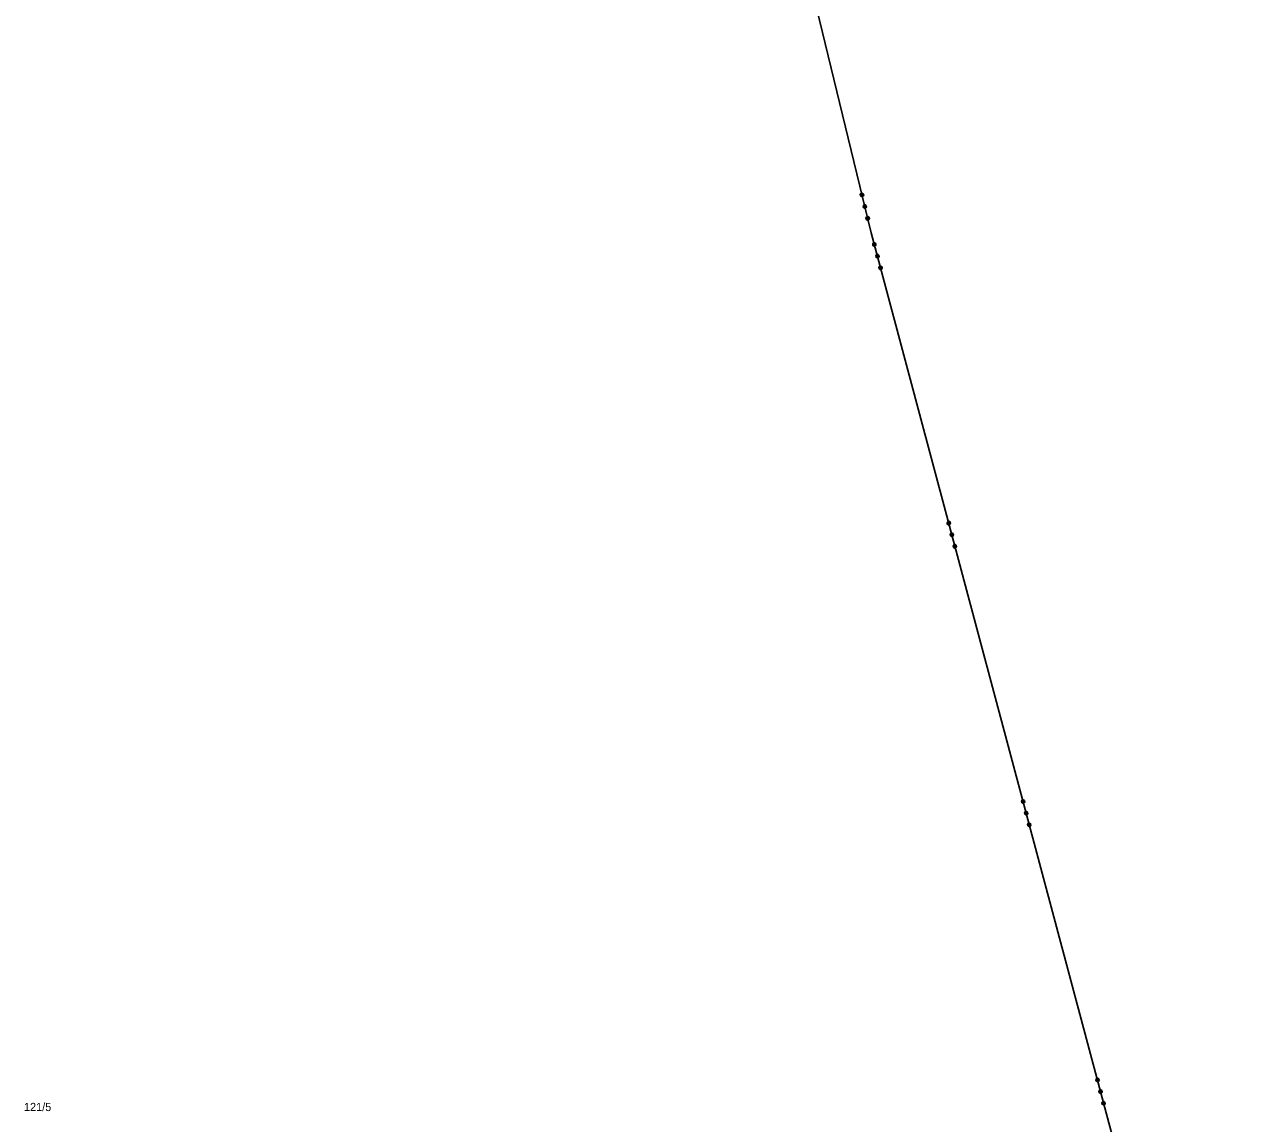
# Model space of a CAD drawing. Extents: x -757994 to -755874, y -1047691 to -1046119.
# Drawn here: x -756034.7 to -755905.7, y -1046848.6 to -1046734.2 of the extents above; entities that cross this region are included whole.
import ezdxf

# ---------------------------------------------------------------- set-up
doc = ezdxf.new("R2010")
doc.units = 0
doc.layers.add('katastrální mapa', color=7, linetype='Continuous')

msp = doc.modelspace()

# ---------------------------------------------------------------- linework, layer by layer
at = {"layer": 'katastrální mapa'}
for p, q in [((-755983.3, -1046604.98), (-755946.55, -1046755.9)), ((-755946.55, -1046755.9), (-755905.73, -1046908.68))]:
    msp.add_line(p, q, dxfattribs=at)
for points in [[(-755947.34, -1046751.96), (-755947.41, -1046752.08), (-755947.55, -1046752.11), (-755947.66, -1046752.04), (-755947.69, -1046751.91), (-755947.62, -1046751.79), (-755947.49, -1046751.76), (-755947.38, -1046751.83), (-755947.34, -1046751.96), (-755947.36, -1046751.97), (-755947.39, -1046751.85), (-755947.44, -1046751.82), (-755947.39, -1046752.02), (-755947.42, -1046752.06), (-755947.49, -1046751.8), (-755947.53, -1046751.8), (-755947.46, -1046752.06), (-755947.5, -1046752.08), (-755947.56, -1046751.82), (-755947.6, -1046751.83), (-755947.54, -1046752.09), (-755947.58, -1046752.07), (-755947.64, -1046751.86), (-755947.67, -1046751.91), (-755947.63, -1046752.04)], [(-755947.05, -1046753.18), (-755947.12, -1046753.3), (-755947.25, -1046753.33), (-755947.36, -1046753.26), (-755947.4, -1046753.13), (-755947.33, -1046753.01), (-755947.19, -1046752.98), (-755947.08, -1046753.05), (-755947.05, -1046753.18), (-755947.07, -1046753.18), (-755947.1, -1046753.06), (-755947.14, -1046753.03), (-755947.1, -1046753.23), (-755947.13, -1046753.28), (-755947.19, -1046753), (-755947.23, -1046753.01), (-755947.17, -1046753.29), (-755947.2, -1046753.3), (-755947.27, -1046753.02), (-755947.31, -1046753.03), (-755947.24, -1046753.31), (-755947.29, -1046753.28), (-755947.34, -1046753.08), (-755947.37, -1046753.13), (-755947.34, -1046753.25)], [(-755946.75, -1046754.4), (-755946.82, -1046754.51), (-755946.95, -1046754.55), (-755947.07, -1046754.48), (-755947.1, -1046754.35), (-755947.03, -1046754.23), (-755946.9, -1046754.2), (-755946.78, -1046754.27), (-755946.75, -1046754.4), (-755946.78, -1046754.39), (-755946.8, -1046754.27), (-755946.85, -1046754.25), (-755946.8, -1046754.43), (-755946.83, -1046754.48), (-755946.9, -1046754.23), (-755946.93, -1046754.24), (-755946.87, -1046754.49), (-755946.91, -1046754.5), (-755946.97, -1046754.25), (-755947.01, -1046754.25), (-755946.95, -1046754.51), (-755947, -1046754.5), (-755947.04, -1046754.3), (-755947.08, -1046754.33), (-755947.05, -1046754.45)], [(-755946.06, -1046757.13), (-755946.12, -1046757.25), (-755946.25, -1046757.28), (-755946.37, -1046757.21), (-755946.4, -1046757.08), (-755946.34, -1046756.97), (-755946.21, -1046756.93), (-755946.09, -1046757), (-755946.06, -1046757.13), (-755946.07, -1046757.14), (-755946.1, -1046757.02), (-755946.15, -1046756.99), (-755946.1, -1046757.19), (-755946.13, -1046757.23), (-755946.2, -1046756.97), (-755946.24, -1046756.98), (-755946.17, -1046757.23), (-755946.21, -1046757.25), (-755946.28, -1046756.99), (-755946.32, -1046757), (-755946.25, -1046757.26), (-755946.29, -1046757.24), (-755946.35, -1046757.04), (-755946.38, -1046757.08), (-755946.34, -1046757.22)], [(-755945.73, -1046758.34), (-755945.8, -1046758.46), (-755945.93, -1046758.49), (-755946.05, -1046758.43), (-755946.08, -1046758.29), (-755946.01, -1046758.18), (-755945.88, -1046758.14), (-755945.77, -1046758.21), (-755945.73, -1046758.34), (-755945.75, -1046758.34), (-755945.78, -1046758.23), (-755945.83, -1046758.2), (-755945.78, -1046758.39), (-755945.81, -1046758.44), (-755945.88, -1046758.17), (-755945.92, -1046758.18), (-755945.85, -1046758.45), (-755945.89, -1046758.46), (-755945.96, -1046758.19), (-755946, -1046758.2), (-755945.93, -1046758.47), (-755945.97, -1046758.44), (-755946.03, -1046758.25), (-755946.05, -1046758.3), (-755946.02, -1046758.41)], [(-755945.41, -1046759.55), (-755945.48, -1046759.67), (-755945.61, -1046759.71), (-755945.72, -1046759.64), (-755945.76, -1046759.51), (-755945.69, -1046759.39), (-755945.56, -1046759.36), (-755945.44, -1046759.42), (-755945.41, -1046759.55), (-755945.43, -1046759.54), (-755945.46, -1046759.42), (-755945.51, -1046759.41), (-755945.46, -1046759.59), (-755945.49, -1046759.64), (-755945.56, -1046759.39), (-755945.6, -1046759.4), (-755945.53, -1046759.65), (-755945.57, -1046759.66), (-755945.63, -1046759.41), (-755945.67, -1046759.41), (-755945.61, -1046759.66), (-755945.65, -1046759.66), (-755945.7, -1046759.46), (-755945.74, -1046759.49), (-755945.7, -1046759.61)], [(-755938.31, -1046786.11), (-755938.38, -1046786.23), (-755938.51, -1046786.26), (-755938.63, -1046786.2), (-755938.66, -1046786.07), (-755938.59, -1046785.95), (-755938.46, -1046785.91), (-755938.35, -1046785.98), (-755938.31, -1046786.11), (-755938.33, -1046786.12), (-755938.36, -1046786.01), (-755938.41, -1046785.98), (-755938.36, -1046786.17), (-755938.39, -1046786.21), (-755938.46, -1046785.95), (-755938.5, -1046785.96), (-755938.43, -1046786.22), (-755938.47, -1046786.23), (-755938.53, -1046785.98), (-755938.57, -1046785.99), (-755938.5, -1046786.24), (-755938.55, -1046786.23), (-755938.61, -1046786.02), (-755938.63, -1046786.06), (-755938.6, -1046786.2)], [(-755937.99, -1046787.33), (-755938.06, -1046787.44), (-755938.19, -1046787.48), (-755938.3, -1046787.41), (-755938.34, -1046787.28), (-755938.27, -1046787.16), (-755938.14, -1046787.13), (-755938.02, -1046787.19), (-755937.99, -1046787.33), (-755938.01, -1046787.33), (-755938.04, -1046787.21), (-755938.09, -1046787.18), (-755938.04, -1046787.37), (-755938.07, -1046787.42), (-755938.14, -1046787.15), (-755938.18, -1046787.16), (-755938.1, -1046787.43), (-755938.14, -1046787.44), (-755938.21, -1046787.17), (-755938.25, -1046787.18), (-755938.18, -1046787.45), (-755938.23, -1046787.43), (-755938.28, -1046787.23), (-755938.31, -1046787.28), (-755938.28, -1046787.4)], [(-755937.66, -1046788.54), (-755937.73, -1046788.65), (-755937.86, -1046788.69), (-755937.98, -1046788.62), (-755938.01, -1046788.49), (-755937.95, -1046788.37), (-755937.82, -1046788.34), (-755937.7, -1046788.41), (-755937.66, -1046788.54), (-755937.69, -1046788.52), (-755937.72, -1046788.41), (-755937.77, -1046788.39), (-755937.72, -1046788.57), (-755937.75, -1046788.62), (-755937.81, -1046788.37), (-755937.85, -1046788.38), (-755937.78, -1046788.63), (-755937.82, -1046788.64), (-755937.89, -1046788.39), (-755937.93, -1046788.4), (-755937.86, -1046788.65), (-755937.91, -1046788.64), (-755937.96, -1046788.44), (-755937.99, -1046788.47), (-755937.96, -1046788.59)], [(-755930.57, -1046815.1), (-755930.64, -1046815.21), (-755930.77, -1046815.25), (-755930.88, -1046815.18), (-755930.92, -1046815.05), (-755930.85, -1046814.93), (-755930.72, -1046814.9), (-755930.6, -1046814.97), (-755930.57, -1046815.1), (-755930.59, -1046815.11), (-755930.62, -1046814.99), (-755930.67, -1046814.96), (-755930.61, -1046815.15), (-755930.65, -1046815.19), (-755930.71, -1046814.93), (-755930.75, -1046814.94), (-755930.69, -1046815.2), (-755930.72, -1046815.21), (-755930.79, -1046814.96), (-755930.83, -1046814.97), (-755930.76, -1046815.22), (-755930.81, -1046815.21), (-755930.86, -1046815), (-755930.89, -1046815.05), (-755930.86, -1046815.18)], [(-755930.24, -1046816.31), (-755930.31, -1046816.42), (-755930.44, -1046816.46), (-755930.56, -1046816.39), (-755930.59, -1046816.26), (-755930.53, -1046816.15), (-755930.4, -1046816.11), (-755930.28, -1046816.18), (-755930.24, -1046816.31), (-755930.27, -1046816.31), (-755930.3, -1046816.19), (-755930.34, -1046816.16), (-755930.29, -1046816.36), (-755930.32, -1046816.41), (-755930.39, -1046816.14), (-755930.43, -1046816.15), (-755930.36, -1046816.42), (-755930.4, -1046816.43), (-755930.47, -1046816.16), (-755930.51, -1046816.17), (-755930.44, -1046816.44), (-755930.49, -1046816.41), (-755930.54, -1046816.22), (-755930.57, -1046816.26), (-755930.54, -1046816.38)], [(-755929.92, -1046817.52), (-755929.99, -1046817.64), (-755930.12, -1046817.67), (-755930.24, -1046817.6), (-755930.27, -1046817.47), (-755930.2, -1046817.36), (-755930.07, -1046817.32), (-755929.96, -1046817.39), (-755929.92, -1046817.52), (-755929.95, -1046817.51), (-755929.98, -1046817.39), (-755930.02, -1046817.37), (-755929.97, -1046817.56), (-755930, -1046817.6), (-755930.07, -1046817.35), (-755930.11, -1046817.36), (-755930.04, -1046817.62), (-755930.08, -1046817.63), (-755930.15, -1046817.37), (-755930.19, -1046817.38), (-755930.12, -1046817.63), (-755930.16, -1046817.62), (-755930.22, -1046817.42), (-755930.25, -1046817.46), (-755930.22, -1046817.57)], [(-755922.82, -1046844.08), (-755922.89, -1046844.2), (-755923.02, -1046844.23), (-755923.14, -1046844.16), (-755923.17, -1046844.03), (-755923.11, -1046843.92), (-755922.98, -1046843.88), (-755922.86, -1046843.95), (-755922.82, -1046844.08), (-755922.84, -1046844.09), (-755922.87, -1046843.97), (-755922.92, -1046843.94), (-755922.87, -1046844.14), (-755922.9, -1046844.18), (-755922.97, -1046843.92), (-755923.01, -1046843.93), (-755922.94, -1046844.18), (-755922.98, -1046844.2), (-755923.05, -1046843.94), (-755923.09, -1046843.95), (-755923.02, -1046844.21), (-755923.06, -1046844.19), (-755923.12, -1046843.99), (-755923.15, -1046844.03), (-755923.11, -1046844.17)], [(-755922.5, -1046845.29), (-755922.57, -1046845.41), (-755922.7, -1046845.44), (-755922.81, -1046845.38), (-755922.85, -1046845.24), (-755922.78, -1046845.13), (-755922.65, -1046845.09), (-755922.54, -1046845.16), (-755922.5, -1046845.29), (-755922.52, -1046845.29), (-755922.55, -1046845.18), (-755922.6, -1046845.15), (-755922.55, -1046845.34), (-755922.58, -1046845.39), (-755922.65, -1046845.12), (-755922.69, -1046845.13), (-755922.62, -1046845.4), (-755922.66, -1046845.41), (-755922.73, -1046845.14), (-755922.77, -1046845.15), (-755922.69, -1046845.42), (-755922.74, -1046845.39), (-755922.79, -1046845.2), (-755922.82, -1046845.25), (-755922.79, -1046845.36)], [(-755922.18, -1046846.5), (-755922.24, -1046846.62), (-755922.37, -1046846.66), (-755922.49, -1046846.59), (-755922.53, -1046846.46), (-755922.46, -1046846.34), (-755922.33, -1046846.31), (-755922.21, -1046846.37), (-755922.18, -1046846.5), (-755922.2, -1046846.49), (-755922.23, -1046846.37), (-755922.28, -1046846.36), (-755922.23, -1046846.54), (-755922.26, -1046846.59), (-755922.33, -1046846.34), (-755922.36, -1046846.35), (-755922.3, -1046846.6), (-755922.34, -1046846.61), (-755922.4, -1046846.36), (-755922.44, -1046846.36), (-755922.38, -1046846.61), (-755922.42, -1046846.61), (-755922.47, -1046846.41), (-755922.5, -1046846.44), (-755922.47, -1046846.56)]]:
    msp.add_lwpolyline(points, dxfattribs=at)

# ---------------------------------------------------------------- texts
msp.add_text('121/5', height=0.85, dxfattribs=at).set_placement((-756034.79, -1046847.29))

doc.saveas('drawing.dxf')
